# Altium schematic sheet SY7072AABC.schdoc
size 127 x 101 mm
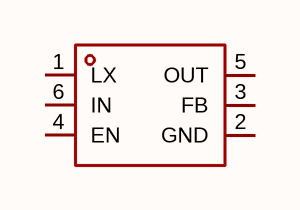
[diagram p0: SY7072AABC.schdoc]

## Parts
U?  sy7072aabc  [SOT-23-6_L2.9-W1.6-P0.95-LS2.8-BL]  (value not drawn)

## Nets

Not connected (* = marked no-connect by the designer): U? 1(LX) 2(GND) 3(FB) 4(EN) 5(OUT) 6(IN)

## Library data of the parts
U? = sy7072aabc: 功能类型:升压型;工作电压:850mV~5.5V;输出电压:1.8V~5.5V;输出电流:2A;输出类型:可调;; Manufacturer: Silergy(矽力杰); AddInBom: yes; ModelId: 18da8f6c14a34920b3e136b5c401a119; ModelName: SOT-23-6_L2.9-W1.6-H1.5-LS2.8-P0.95; ModelTransform: 110.236,113.364,0,90,0,0,0.0005,0.0005,0; Function: 升压型; Output Current: 2A; Frequency - Switching: 1MHz; Synchronous Rectifier: 是; Number of Outputs: 1; Topology: 升压式; Quiescent Current: 5uA; Switch tube (built-in/external): 内置; Output Type: 可调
